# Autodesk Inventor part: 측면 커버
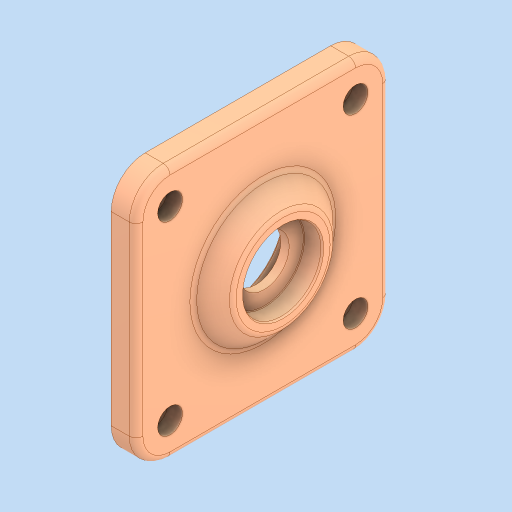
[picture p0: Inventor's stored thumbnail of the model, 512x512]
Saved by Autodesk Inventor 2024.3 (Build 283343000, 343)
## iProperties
Created: 2026-01
Part Number: 측면 커버
Material: 알루미늄 6061
Document SubType Name: Modeling
Designer: PC2-02
Density: 2.7 g/cm^3
Appearance: 기본값
Author: jhkim
Sending System: Autodesk Inventor 2026
Preprocessor: ST-DEVELOPER v20.1
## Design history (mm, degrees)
node "측면 커버1"
node "솔리드2"
node "솔리드1"
